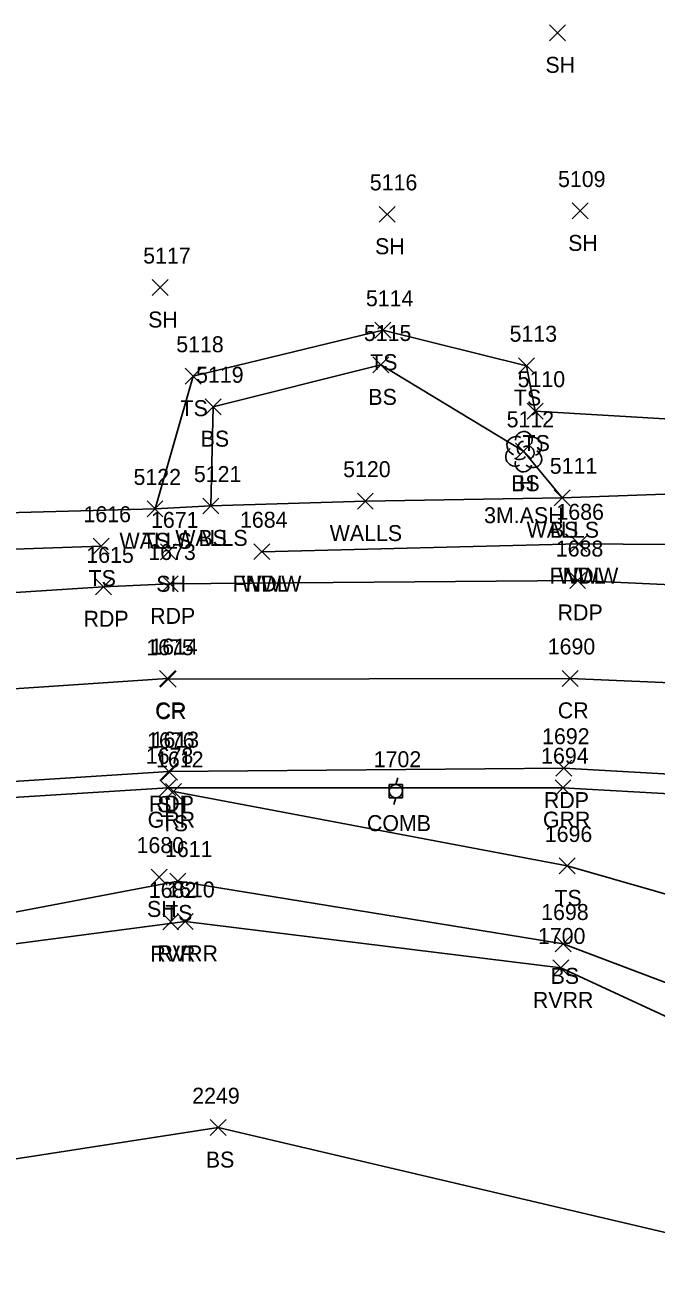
# Model space of a CAD drawing. Extents: x 1509053 to 1511576, y 400838 to 402572.
# Drawn here: x 1510202.2 to 1510281.3, y 401581.3 to 401737.4 of the extents above; entities that cross this region are included whole.
import ezdxf

# ---------------------------------------------------------------- set-up
doc = ezdxf.new("R2010")
doc.units = 0
for name, color, linetype in [('L_A', 7, 'Continuous'), ('L_C', 7, 'Continuous'), ('L_I', 7, 'Continuous'), ('L_TIC', 7, 'Continuous'), ('LAWE', 7, 'Continuous'), ('LELB', 7, 'Continuous'), ('LFNC', 7, 'Continuous'), ('LTD', 7, 'Continuous'), ('LWS', 7, 'Continuous'), ('P_A', 7, 'Continuous'), ('P_I', 7, 'Continuous'), ('P_TIC', 7, 'Continuous'), ('PET', 7, 'Continuous'), ('PRC', 7, 'Continuous'), ('R_A', 7, 'Continuous'), ('R_I', 7, 'Continuous'), ('R_TIC', 7, 'Continuous'), ('RGR', 7, 'Continuous'), ('U_A', 7, 'Continuous'), ('U_I', 7, 'Continuous'), ('UP', 7, 'Continuous')]:
    doc.layers.add(name, color=color, linetype=linetype)

msp = doc.modelspace()

# ---------------------------------------------------------------- linework, layer by layer
at = {"layer": 'L_TIC'}
for points in [[(1510267.91, 401735.36), (1510269.91, 401737.36)], [(1510269.91, 401735.36), (1510267.91, 401737.36)], [(1510246.58, 401712.64), (1510248.58, 401714.64)], [(1510248.58, 401712.64), (1510246.58, 401714.64)], [(1510270.76, 401713.06), (1510272.76, 401715.06)], [(1510272.76, 401713.06), (1510270.76, 401715.06)], [(1510218.14, 401703.47), (1510220.14, 401705.47)], [(1510220.14, 401703.47), (1510218.14, 401705.47)], [(1510246.04, 401698.13), (1510248.04, 401700.13)], [(1510248.04, 401698.13), (1510246.04, 401700.13)], [(1510245.78, 401693.78), (1510247.78, 401695.78)], [(1510247.78, 401693.78), (1510245.78, 401695.78)], [(1510264.04, 401693.69), (1510266.04, 401695.69)], [(1510266.04, 401693.69), (1510264.04, 401695.69)], [(1510222.28, 401692.37), (1510224.28, 401694.37)], [(1510224.28, 401692.37), (1510222.28, 401694.37)], [(1510224.77, 401688.55), (1510226.77, 401690.55)], [(1510226.77, 401688.55), (1510224.77, 401690.55)], [(1510265.13, 401688), (1510267.13, 401690)], [(1510267.13, 401688), (1510265.13, 401690)], [(1510263.66, 401682.97), (1510265.66, 401684.97)], [(1510265.66, 401682.97), (1510263.66, 401684.97)], [(1510243.84, 401676.73), (1510245.84, 401678.73)], [(1510245.84, 401676.73), (1510243.84, 401678.73)], [(1510268.51, 401677.15), (1510270.51, 401679.15)], [(1510270.51, 401677.15), (1510268.51, 401679.15)], [(1510268.51, 401677.15), (1510270.51, 401679.15)], [(1510270.51, 401677.15), (1510268.51, 401679.15)], [(1510217.49, 401675.76), (1510219.49, 401677.76)], [(1510219.49, 401675.76), (1510217.49, 401677.76)], [(1510217.49, 401675.76), (1510219.49, 401677.76)], [(1510219.49, 401675.76), (1510217.49, 401677.76)], [(1510224.49, 401676.12), (1510226.49, 401678.12)], [(1510226.49, 401676.12), (1510224.49, 401678.12)], [(1510224.49, 401676.12), (1510226.49, 401678.12)], [(1510226.49, 401676.12), (1510224.49, 401678.12)], [(1510210.76, 401671.09), (1510212.76, 401673.09)], [(1510212.76, 401671.09), (1510210.76, 401673.09)], [(1510219.16, 401670.38), (1510221.16, 401672.38)], [(1510221.16, 401670.38), (1510219.16, 401672.38)], [(1510230.88, 401670.4), (1510232.88, 401672.4)], [(1510232.88, 401670.4), (1510230.88, 401672.4)], [(1510230.88, 401670.4), (1510232.88, 401672.4)], [(1510232.88, 401670.4), (1510230.88, 401672.4)], [(1510270.57, 401671.39), (1510272.57, 401673.39)], [(1510272.57, 401671.39), (1510270.57, 401673.39)], [(1510270.57, 401671.39), (1510272.57, 401673.39)], [(1510272.57, 401671.39), (1510270.57, 401673.39)], [(1510219.3, 401642.78), (1510221.3, 401644.78)], [(1510221.3, 401642.78), (1510219.3, 401644.78)], [(1510219.79, 401640.39), (1510221.79, 401642.39)], [(1510221.79, 401640.39), (1510219.79, 401642.39)], [(1510269.12, 401631.05), (1510271.12, 401633.05)], [(1510271.12, 401631.05), (1510269.12, 401633.05)], [(1510218, 401629.66), (1510220, 401631.66)], [(1510220, 401629.66), (1510218, 401631.66)], [(1510220.35, 401629.16), (1510222.35, 401631.16)], [(1510222.35, 401629.16), (1510220.35, 401631.16)], [(1510219.46, 401624.05), (1510221.45, 401626.05)], [(1510221.45, 401624.05), (1510219.46, 401626.05)], [(1510221.28, 401624.1), (1510223.28, 401626.1)], [(1510223.28, 401624.1), (1510221.28, 401626.1)], [(1510268.61, 401621.28), (1510270.61, 401623.28)], [(1510270.61, 401621.28), (1510268.61, 401623.28)], [(1510268.32, 401618.27), (1510270.32, 401620.28)], [(1510270.32, 401618.27), (1510268.32, 401620.28)], [(1510225.42, 401598.28), (1510227.42, 401600.28)], [(1510227.42, 401598.28), (1510225.42, 401600.28)]]:
    msp.add_lwpolyline(points, dxfattribs=at)
at = {"layer": 'LAWE'}
msp.add_lwpolyline([(1510071.34, 401620.03), (1510084.03, 401618.47), (1510124.74, 401612.27), (1510171.7, 401618.45), (1510222.28, 401625.1), (1510269.32, 401619.28), (1510308.65, 401601.1)], dxfattribs=at)
at = {"layer": 'LELB'}
for points in [[(1510431.72, 401516.61), (1510341.14, 401547.81), (1510292.56, 401583.77), (1510226.42, 401599.28), (1510151.75, 401587.72), (1510095.68, 401580.81), (1510017.56, 401603.54), (1510015.48, 401644.92), (1509989.35, 401675.01), (1509940.27, 401707.21)], [(1510337.11, 401685.04), (1510326.18, 401689.24), (1510303.56, 401686.79), (1510266.13, 401689), (1510265.04, 401694.69), (1510247.04, 401699.13), (1510223.28, 401693.37), (1510218.49, 401676.76)], [(1510269.51, 401678.15), (1510264.66, 401683.97), (1510246.78, 401694.78), (1510225.77, 401689.55), (1510225.49, 401677.12)], [(1510211.76, 401672.09), (1510193.59, 401671.47)], [(1510220.79, 401641.39), (1510270.12, 401632.05), (1510320.96, 401617.48), (1510371.68, 401612.92)], [(1510171.73, 401620.69), (1510221.35, 401630.16)], [(1510221.35, 401630.16), (1510269.61, 401622.28)], [(1510269.61, 401622.28), (1510312.14, 401606.21)]]:
    msp.add_lwpolyline(points, dxfattribs=at)
at = {"layer": 'LFNC'}
msp.add_lwpolyline([(1510231.88, 401671.4), (1510271.57, 401672.39), (1510321.6, 401672.01), (1510335.01, 401672.93)], dxfattribs=at)
at = {"layer": 'LTD'}
msp.add_line((1510264.66, 401683.97), (1510264.66, 401683.97), dxfattribs=at)
msp.add_line((1510264.66, 401683.97), (1510264.66, 401683.97), dxfattribs=at)
msp.add_arc((1510264.71, 401685.4), 1.05, 335.5272, 180.9563, dxfattribs=at)
for centre, major_axis, ratio, start_param, end_param in [((1510263.87, 401684.63), (1.21, -0.51), 0.895232, 1.570796, 4.712389), ((1510264.46, 401684.42), (-0.208, -0.792), 0.645439, 3.141593, 6.283185), ((1510265.16, 401683.8), (-0.5, 0.667), 0.989748, 3.141593, 6.283185), ((1510265.71, 401684.55), (-1.14, -0.48), 0.949671, 1.570796, 4.712389), ((1510263.58, 401683.26), (0.58, -1.04), 0.959034, 3.141593, 6.283185), ((1510264.21, 401683.22), (-0.625, -0.083), 0.423636, 0, 3.141593), ((1510265.66, 401683.13), (-1.09, 0.79), 0.841452, 1.570796, 4.712389), ((1510264.66, 401682.47), (0.26, 1.06), 0.942809, 1.570796, 4.712389)]:
    msp.add_ellipse(centre, major_axis=major_axis, ratio=ratio, start_param=start_param, end_param=end_param, dxfattribs=at)
at = {"layer": 'LWS'}
msp.add_lwpolyline([(1510349.81, 401679.3), (1510337.11, 401685.04), (1510331.2, 401679.18), (1510316.95, 401676.48), (1510297.59, 401679.14), (1510269.51, 401678.15), (1510244.84, 401677.73), (1510225.49, 401677.12), (1510218.49, 401676.76), (1510185.87, 401675.88)], dxfattribs=at)
at = {"layer": 'P_TIC'}
for points in [[(1510211.05, 401666), (1510213.05, 401668)], [(1510213.05, 401666), (1510211.05, 401668)], [(1510219.39, 401666.36), (1510221.39, 401668.36)], [(1510221.39, 401666.36), (1510219.39, 401668.36)], [(1510270.44, 401666.79), (1510272.44, 401668.79)], [(1510272.44, 401666.79), (1510270.44, 401668.79)], [(1510219.07, 401654.52), (1510221.07, 401656.52)], [(1510221.07, 401654.52), (1510219.07, 401656.52)], [(1510219.14, 401654.43), (1510221.14, 401656.43)], [(1510221.14, 401654.43), (1510219.14, 401656.43)], [(1510269.51, 401654.53), (1510271.51, 401656.53)], [(1510271.51, 401654.53), (1510269.51, 401656.53)], [(1510219.23, 401642.86), (1510221.23, 401644.86)], [(1510221.23, 401642.86), (1510219.23, 401644.86)], [(1510268.72, 401643.29), (1510270.72, 401645.29)], [(1510270.72, 401643.29), (1510268.72, 401645.29)]]:
    msp.add_lwpolyline(points, dxfattribs=at)
at = {"layer": 'PET'}
for points in [[(1510068.52, 401654.76), (1510069.7, 401647.38), (1510117.95, 401657.12), (1510168.51, 401664.21), (1510212.05, 401667), (1510220.39, 401667.36), (1510271.44, 401667.79), (1510321.9, 401665.44), (1510371.76, 401662.64), (1510420.35, 401661.34), (1510470.43, 401662.43), (1510520.33, 401664.72), (1510570.63, 401667.06), (1510593.1, 401669.05), (1510621.58, 401670.53), (1510656.11, 401672.66)], [(1510069.7, 401647.38), (1510070.82, 401637.95), (1510072.41, 401628.04), (1510122.3, 401634.81), (1510170.19, 401640.65), (1510220.23, 401643.86), (1510269.72, 401644.29), (1510320.63, 401641.42), (1510370.24, 401637.87), (1510421.73, 401637.03), (1510472.3, 401638.25), (1510523.24, 401640.81), (1510571.7, 401643.53), (1510622.45, 401646.41), (1510672.72, 401649.13), (1510722.86, 401651.91), (1510723.41, 401651.94), (1510773.15, 401654.37), (1510822.4, 401657.74), (1510872.35, 401660.8), (1510922.85, 401663.95), (1510967.23, 401666.49), (1511034, 401670.65), (1511071.49, 401673.22)]]:
    msp.add_lwpolyline(points, dxfattribs=at)
at = {"layer": 'PRC'}
msp.add_lwpolyline([(1510070.82, 401637.95), (1510120.23, 401645.42), (1510169.76, 401652.13), (1510220.07, 401655.52), (1510220.14, 401655.43), (1510270.51, 401655.53), (1510320.84, 401653.34), (1510371.03, 401650.53), (1510421.26, 401649.11), (1510471.33, 401650.1), (1510521.34, 401652.38), (1510571.58, 401655.12), (1510621.67, 401657.75), (1510671.66, 401660.66), (1510722.15, 401663.46), (1510772.15, 401666.42), (1510822.28, 401669.1), (1510872.26, 401671.98), (1510872.29, 401672.01), (1510922.21, 401674.96), (1510971.31, 401678.08), (1511022.51, 401681.61), (1511070.2, 401684.98)], dxfattribs=at)
at = {"layer": 'R_TIC'}
for points in [[(1510219.08, 401640.84), (1510221.08, 401642.84)], [(1510221.08, 401640.84), (1510219.08, 401642.84)], [(1510268.6, 401640.85), (1510270.6, 401642.85)], [(1510270.6, 401640.85), (1510268.6, 401642.85)]]:
    msp.add_lwpolyline(points, dxfattribs=at)
at = {"layer": 'RGR'}
msp.add_lwpolyline([(1510073.99, 401627.51), (1510122.46, 401632.98), (1510170.64, 401638.74), (1510220.08, 401641.84), (1510269.6, 401641.85), (1510311.11, 401639.49), (1510334.05, 401636.42), (1510370.16, 401634.91), (1510403.15, 401632.59)], dxfattribs=at)
at = {"layer": 'UP'}
for p, q in [((1510248.91, 401643.08), (1510248.66, 401642.25)), ((1510247.82, 401640.58), (1510247.82, 401642.25)), ((1510247.82, 401642.25), (1510249.49, 401642.25)), ((1510248.66, 401641.41), (1510248.66, 401641.41)), ((1510249.49, 401642.25), (1510249.49, 401640.58)), ((1510249.49, 401640.58), (1510247.82, 401640.58)), ((1510248.41, 401639.75), (1510248.66, 401640.58))]:
    msp.add_line(p, q, dxfattribs=at)
msp.add_circle((1510248.66, 401641.41), 0.833, dxfattribs=at)

# ---------------------------------------------------------------- texts
at = {"layer": 'L_A'}
for s, p in [('SH', (1510267.4, 401731.36)), ('SH', (1510246.06, 401708.64)), ('SH', (1510270.25, 401709.06)), ('SH', (1510217.63, 401699.47)), ('TS', (1510245.45, 401694.13)), ('BS', (1510245.22, 401689.78)), ('TS', (1510263.45, 401689.69)), ('TS', (1510221.69, 401688.37)), ('BS', (1510224.21, 401684.55)), ('TS', (1510264.54, 401684)), ('BS', (1510263.11, 401678.97)), ('H', (1510264.1, 401678.97)), ('WALLS', (1510221.03, 401672.12)), ('BS', (1510223.93, 401672.12)), ('WALLS', (1510240.38, 401672.73)), ('WALLS', (1510265.05, 401673.15)), ('BS', (1510267.95, 401673.15)), ('WALLS', (1510214.04, 401671.76)), ('TS', (1510216.9, 401671.76)), ('TS', (1510210.17, 401667.09)), ('FNWW', (1510267.92, 401667.39)), ('WDL', (1510268.99, 401667.39)), ('SH', (1510218.65, 401666.38)), ('FNWW', (1510228.22, 401666.4)), ('WDL', (1510229.29, 401666.4)), ('SH', (1510218.78, 401638.78)), ('TS', (1510219.2, 401636.39)), ('TS', (1510268.53, 401627.05)), ('SH', (1510217.49, 401625.66)), ('TS', (1510219.76, 401625.16)), ('RVR', (1510217.91, 401620.05)), ('RVRR', (1510218.79, 401620.1)), ('BS', (1510268.05, 401617.28)), ('RVRR', (1510265.83, 401614.27)), ('BS', (1510224.86, 401594.28))]:
    msp.add_text(s, height=2, dxfattribs=at).set_placement(p)
at = {"layer": 'L_C'}
msp.add_text('3M.ASH', height=2, dxfattribs=at).set_placement((1510259.72, 401674.97))
at = {"layer": 'L_I'}
for s, p in [('5109', (1510268.98, 401717.06)), ('5116', (1510245.4, 401716.64)), ('5117', (1510217.01, 401707.47)), ('5114', (1510244.91, 401702.13)), ('5115', (1510244.66, 401697.78)), ('5113', (1510262.91, 401697.69)), ('5118', (1510221.15, 401696.37)), ('5119', (1510223.64, 401692.55)), ('5110', (1510263.92, 401692)), ('5112', (1510262.54, 401686.97)), ('5112', (1510262.54, 401686.97)), ('5122', (1510215.8, 401679.76)), ('5122', (1510215.8, 401679.76)), ('5121', (1510223.36, 401680.12)), ('5121', (1510223.36, 401680.12)), ('5120', (1510242.06, 401680.73)), ('5111', (1510267.95, 401681.15)), ('5111', (1510267.95, 401681.15)), ('1616', (1510209.53, 401675.09)), ('1686', (1510268.78, 401675.39)), ('1686', (1510268.78, 401675.39)), ('1671', (1510217.99, 401674.38)), ('1684', (1510229.14, 401674.4)), ('1684', (1510229.14, 401674.4)), ('1676', (1510217.5, 401646.78)), ('1612', (1510218.62, 401644.39)), ('1696', (1510267.32, 401635.05)), ('1680', (1510216.18, 401633.66)), ('1611', (1510219.74, 401633.16)), ('1610', (1510220.02, 401628.1)), ('1682', (1510217.71, 401628.05)), ('1698', (1510266.87, 401625.28)), ('1700', (1510266.46, 401622.28)), ('2249', (1510223.15, 401602.28))]:
    msp.add_text(s, height=2, dxfattribs=at).set_placement(p)
at = {"layer": 'P_A'}
for s, p in [('RDP', (1510268.93, 401662.79)), ('RDP', (1510209.54, 401662)), ('RDP', (1510217.88, 401662.36)), ('CR', (1510218.5, 401650.52)), ('CR', (1510218.57, 401650.43)), ('CR', (1510268.95, 401650.53)), ('RDP', (1510267.21, 401639.29)), ('RDP', (1510217.72, 401638.86))]:
    msp.add_text(s, height=2, dxfattribs=at).set_placement(p)
at = {"layer": 'P_I'}
for s, p in [('1673', (1510217.65, 401670.36)), ('1688', (1510268.7, 401670.79)), ('1615', (1510209.88, 401670)), ('1675', (1510217.4, 401658.43)), ('1614', (1510217.9, 401658.52)), ('1690', (1510267.69, 401658.53)), ('1613', (1510218.06, 401646.86)), ('1692', (1510266.98, 401647.29))]:
    msp.add_text(s, height=2, dxfattribs=at).set_placement(p)
at = {"layer": 'R_A'}
for p in [(1510217.57, 401636.84), (1510267.09, 401636.85)]:
    msp.add_text('GRR', height=2, dxfattribs=at).set_placement(p)
at = {"layer": 'R_I'}
for s, p in [('1678', (1510217.34, 401644.84)), ('1694', (1510266.86, 401644.85))]:
    msp.add_text(s, height=2, dxfattribs=at).set_placement(p)
at = {"layer": 'U_A'}
msp.add_text('COMB', height=2, dxfattribs=at).set_placement((1510245.04, 401636.41))
at = {"layer": 'U_I'}
msp.add_text('1702', height=2, dxfattribs=at).set_placement((1510245.89, 401644.41))

doc.saveas('drawing.dxf')
